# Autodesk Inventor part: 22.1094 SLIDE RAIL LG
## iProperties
Created: 2007-06
Part Number: 22.1094 SLIDE RAIL LG
Material: UHMW, Black
Document SubType Name: Modeling
Designer: Andy Moles
Density: 0.94 g/cm^3
Author: Andy Moles
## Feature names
1. Extrusion1
